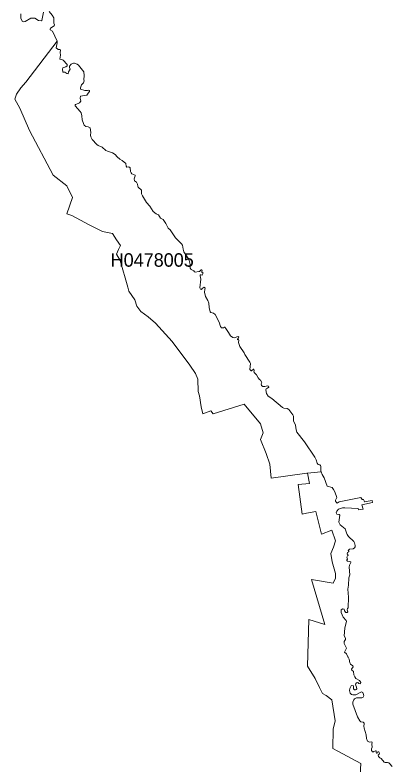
# Model space of a CAD drawing. Extents: x 369010 to 739155, y 6377141 to 6616555.
# Drawn here: x 462164 to 464965, y 6490804 to 6496362 of the extents above; entities that cross this region are included whole.
import ezdxf
from ezdxf.enums import TextEntityAlignment as Align

# ---------------------------------------------------------------- set-up
doc = ezdxf.new("R2010")
doc.units = 0
doc.header["$LTSCALE"] = 40
doc.layers.add('1', color=7, linetype='Continuous', lineweight=13)
doc.layers.add('2', color=7, linetype='Continuous')

msp = doc.modelspace()

# ---------------------------------------------------------------- linework, layer by layer
at = {"layer": '1'}
for points in [[(464337.03, 6491529.74), (464346.14, 6491876.14), (464466.29, 6491840.06), (464366.16, 6492172.56), (464528.52, 6492145.58), (464544.08, 6492181.82), (464544.08, 6492218.07), (464520.74, 6492303.47), (464510.48, 6492365.53), (464531.17, 6492412.21), (464544.08, 6492460.37), (464518.26, 6492537.99), (464440.47, 6492509.52), (464399.1, 6492677.84), (464329.25, 6492664.93), (464298.14, 6492656.82), (464267.19, 6492876.94), (464352.59, 6492884.72), (464337.03, 6492962.17), (464337.03, 6492962.34), (464333.23, 6492961.84), (464067.26, 6492926.09), (464057.5, 6493029.53), (464029.03, 6493107.32), (463987.65, 6493210.76), (464008.34, 6493262.56), (463988.65, 6493327.11), (463867.17, 6493474.58), (463636.79, 6493403.24), (463620.07, 6493424.59), (463559.5, 6493402.25), (463548.08, 6493454.22), (463535, 6493535.48), (463525.57, 6493566.93), (463522.59, 6493659.11), (463504.88, 6493700.98), (463463.34, 6493764.37), (463331.43, 6493940.3), (463207.14, 6494075.02), (463152.85, 6494121.53), (463098.57, 6494162.91), (463070.1, 6494201.8), (463055.54, 6494248.47), (463009.03, 6494313.18), (463001.25, 6494341.65), (462944.32, 6494540.92), (462918.5, 6494587.59), (462933.89, 6494621.19), (462946.97, 6494652.3), (462918.5, 6494693.35), (462887.38, 6494740.02), (462814.89, 6494755.58), (462713.94, 6494804.73), (462587.16, 6494874.57), (462549.92, 6494886.16), (462591.13, 6495007.47), (462548.43, 6495094.86), (462447.64, 6495174.3), (462271.21, 6495504.98), (462201.04, 6495669.82), (462163.97, 6495736.35), (462176.38, 6495773.76), (462206.33, 6495821.26), (462243.74, 6495863.63), (462477.1, 6496166.66), (462476.93, 6496168.65), (462442.34, 6496242.13), (462424.3, 6496250.74), (462424.63, 6496259.68), (462428.28, 6496264.15), (462454.43, 6496281.19), (462457.74, 6496288.81), (462452.27, 6496301.38), (462452.94, 6496340.11), (462441.35, 6496359.64), (462417.35, 6496388.44)], [(462376.31, 6496383.31), (462364.23, 6496320.91), (462360.58, 6496317.6), (462337.91, 6496321.24), (462312.59, 6496337.79), (462282.14, 6496338.46), (462240.59, 6496313.13), (462229.34, 6496311.31), (462220.73, 6496314.46), (462206.67, 6496335.97), (462206.33, 6496371.06)], [(462477.1, 6496166.66), (462243.74, 6495863.63), (462206.33, 6495821.26), (462176.38, 6495773.76), (462163.97, 6495736.35), (462201.04, 6495669.82), (462271.21, 6495504.98), (462447.64, 6495174.3), (462548.43, 6495094.86), (462591.13, 6495007.47), (462549.92, 6494886.16), (462587.16, 6494874.57), (462713.94, 6494804.73), (462814.89, 6494755.58), (462887.38, 6494740.02), (462918.5, 6494693.35), (462946.97, 6494652.3), (462933.89, 6494621.19), (462918.5, 6494587.59), (462944.32, 6494540.92), (463001.25, 6494341.65), (463009.03, 6494313.18), (463055.54, 6494248.47), (463070.1, 6494201.8), (463098.57, 6494162.91), (463152.85, 6494121.53), (463207.14, 6494075.02), (463331.43, 6493940.3), (463463.34, 6493764.37), (463504.88, 6493700.98), (463522.59, 6493659.11), (463525.57, 6493566.93), (463535, 6493535.48), (463548.08, 6493454.22), (463559.5, 6493402.25), (463620.07, 6493424.59), (463636.79, 6493403.24), (463867.17, 6493474.58), (463988.65, 6493327.11), (464008.34, 6493262.56), (463987.65, 6493210.76), (464029.03, 6493107.32), (464057.5, 6493029.53), (464067.26, 6492926.09), (464333.23, 6492961.84), (464337.03, 6492962.34), (464337.03, 6492962.17), (464436.67, 6492970.95), (464437.49, 6492971.11), (464436.5, 6492973.59), (464436.83, 6493012.49), (464433.19, 6493019.94), (464429.38, 6493023.25), (464415.32, 6493027.05), (464407.87, 6493035.33), (464402.08, 6493060.15), (464392.48, 6493080.01), (464313.7, 6493193.55), (464258.75, 6493267.2), (464253.29, 6493283.91), (464248.16, 6493317.35), (464233.26, 6493350.78), (464232.6, 6493384.21), (464227.47, 6493395.13), (464197.68, 6493435.02), (464185.76, 6493440.81), (464160.61, 6493444.62), (464151.01, 6493449.42), (464072.89, 6493516.28), (464045.08, 6493534.49), (464033.33, 6493553.19), (464027.87, 6493581.49), (464030.52, 6493587.61), (464041.11, 6493593.41), (464049.39, 6493601.19), (464047.57, 6493608.8), (464040.45, 6493609.79), (464019.27, 6493604.99), (464005.03, 6493606.32), (463995.76, 6493613.43), (463993.78, 6493624.03), (463997.42, 6493635.94), (463986.99, 6493653.15), (463981.53, 6493657.13), (463971.27, 6493670.2), (463959.35, 6493691.22), (463939.82, 6493708.6), (463937.84, 6493714.56), (463939.82, 6493721.67), (463937.84, 6493733.59), (463935.02, 6493734.25), (463920.79, 6493722), (463917.65, 6493722), (463909.21, 6493731.6), (463912.85, 6493776.95), (463909.87, 6493785.39), (463870.31, 6493842.82), (463866.84, 6493855.9), (463833.9, 6493902.57), (463825.29, 6493931.04)], [(462840.05, 6495357.18), (462811.91, 6495380.85), (462783.12, 6495392.44), (462773.19, 6495400.38), (462738.26, 6495439.11), (462727.34, 6495458.97), (462724.86, 6495469.89), (462726.68, 6495489.09), (462725.52, 6495508.29), (462721.55, 6495525.34), (462706.82, 6495532.29), (462689.61, 6495535.27), (462678.35, 6495543.54), (462672.56, 6495555.79), (462663.62, 6495584.59), (462660.81, 6495613.38), (462655.02, 6495635.06), (462647.9, 6495645.99), (462610.83, 6495689.02), (462610.83, 6495694.98), (462612.98, 6495697.62), (462634.49, 6495704.91), (462643.43, 6495711.36), (462653.03, 6495721.95), (462648.89, 6495743.97), (462651.54, 6495760.68), (462697.22, 6495766.14), (462706.82, 6495782.53), (462718.4, 6495794.94), (462717.08, 6495802.72), (462711.95, 6495803.88), (462701.69, 6495801.4), (462682.49, 6495801.06), (462651.54, 6495812.32), (462651.21, 6495822.58), (462658.16, 6495844.92), (462673.55, 6495858), (462678.35, 6495873.39), (462674.55, 6495879.84), (462677.36, 6495913.11), (462675.54, 6495939.43), (462635.82, 6495990.07), (462626.22, 6495997.35), (462607.02, 6496005.13), (462598.25, 6496004.47), (462582.53, 6495996.36), (462570.11, 6495983.28), (462569.12, 6495973.02), (462573.59, 6495960.61), (462561.18, 6495941.41), (462558.53, 6495925.69), (462549.26, 6495926.85), (462535.19, 6495937.44), (462522.78, 6495936.78), (462519.47, 6495938.43), (462516.32, 6495958.96), (462518.48, 6495970.54), (462540.98, 6495978.15), (462552.73, 6495985.6), (462552.73, 6495994.21), (462522.45, 6496026.48), (462512.85, 6496031.28), (462497.79, 6496033.6), (462501.59, 6496064.38), (462500.27, 6496083.58), (462502.26, 6496099.8), (462498.95, 6496104.93), (462484.55, 6496104.93), (462471.14, 6496118.83), (462471.47, 6496131.58), (462478.26, 6496154.91), (462477.1, 6496166.66)], [(463825.29, 6493931.04), (463827.28, 6493949.24), (463824.96, 6493952.72), (463818.01, 6493952.39), (463817.68, 6493956.52), (463824.3, 6493965.79), (463826.62, 6493972.58), (463821.16, 6493977.38), (463811.23, 6493974.73), (463795.17, 6493965.79), (463782.26, 6493967.78), (463764.06, 6493981.51), (463750.98, 6494007), (463729.96, 6494034.81), (463723.84, 6494044.41), (463718.71, 6494045.73), (463714.57, 6494040.27), (463698.85, 6494040.93), (463689.91, 6494051.52), (463681.64, 6494082.8), (463651.52, 6494138.41), (463639.1, 6494150.49), (463618.91, 6494154.13), (463614.11, 6494160.09), (463605.51, 6494190.55), (463603.52, 6494224.14), (463597.73, 6494243.51), (463580.18, 6494272.3), (463572.4, 6494305.57), (463574.06, 6494324.44), (463577.54, 6494334.04), (463570.25, 6494341.65), (463561.65, 6494337.84), (463554.7, 6494331.89), (463550.72, 6494324.44), (463541.12, 6494326.59), (463536.99, 6494338.18), (463543.77, 6494400.57), (463539.64, 6494425.4), (463540.79, 6494433.84), (463546.09, 6494433.34), (463554.03, 6494431.19), (463560.16, 6494440.79), (463559.5, 6494452.54), (463551.22, 6494451.71), (463550.89, 6494457.34), (463555.03, 6494466.28), (463552.54, 6494471.07), (463547.25, 6494469.92), (463535.66, 6494459.16), (463529.7, 6494458.17), (463503.06, 6494453.03), (463496.93, 6494456.84), (463492.14, 6494463.3), (463472.27, 6494473.72), (463465.65, 6494482.83), (463465.99, 6494511.62), (463459.2, 6494540.42), (463453.74, 6494552.83), (463418.49, 6494605.13), (463412.69, 6494624.33), (463408.56, 6494653.13), (463401.94, 6494665.05), (463356.42, 6494709.57), (463316.7, 6494767.82), (463301.31, 6494781.23), (463285.59, 6494815.16), (463264.24, 6494844.45), (463246.2, 6494854.38), (463230.8, 6494878.71), (463212.93, 6494885.33), (463191.08, 6494903.04), (463164.93, 6494943.92), (463141.1, 6494971.56), (463110.48, 6495019.56), (463104.36, 6495034.95), (463104.69, 6495060.93), (463080.03, 6495083.61), (463076.39, 6495092.54), (463075.23, 6495107.6), (463066.29, 6495120.84), (463052.06, 6495131.27), (463049.91, 6495145.67), (463057.85, 6495168.84), (463055.7, 6495174.63), (463032.86, 6495183.24), (463026.24, 6495190.02), (463022.27, 6495201.44), (463018.79, 6495228.75), (463010.52, 6495235.37), (462995.79, 6495232.89), (462990.99, 6495239.84), (462987.18, 6495260.03), (462959.87, 6495281.88), (462942, 6495292.14), (462923.3, 6495309.02), (462908.07, 6495326.73), (462888.71, 6495338.32), (462850.31, 6495351.06), (462840.05, 6495357.18)], [(464437.49, 6492971.11), (464436.67, 6492970.95), (464337.03, 6492962.17), (464352.59, 6492884.72), (464267.19, 6492876.94), (464298.14, 6492656.82), (464329.25, 6492664.93), (464399.1, 6492677.84), (464440.47, 6492509.52), (464518.26, 6492537.99), (464544.08, 6492460.37), (464531.17, 6492412.21), (464510.48, 6492365.53), (464520.74, 6492303.47), (464544.08, 6492218.07), (464544.08, 6492181.82), (464528.52, 6492145.58), (464366.16, 6492172.56), (464466.29, 6491840.06), (464346.14, 6491876.14), (464337.03, 6491529.74), (464393.97, 6491439.04), (464425.08, 6491371.85), (464448.25, 6491327.99), (464476.72, 6491312.6), (464518.26, 6491278.83), (464541.43, 6491123.59), (464528.52, 6491061.36), (464524.55, 6490917.87), (464563.44, 6490898.84), (464733.42, 6490806.98), (464720.01, 6490596.46)], [(464545.73, 6492753.47), (464545.07, 6492762.08), (464553.84, 6492782.44), (464540.93, 6492822.82), (464531.33, 6492841.52), (464520.08, 6492855.42), (464484, 6492865.02), (464461.16, 6492928.41), (464445.44, 6492952.74), (464437.49, 6492971.11)], [(464711.9, 6491408.09), (464719.02, 6491401.64), (464729.61, 6491398.49), (464732.26, 6491407.76), (464723.15, 6491422.99), (464696.51, 6491439.37), (464687.57, 6491450.3), (464681.78, 6491466.68), (464678.3, 6491489.19), (464665.72, 6491499.45), (464665.06, 6491508.06), (464677.31, 6491524.44), (464674.33, 6491532.88), (464656.29, 6491543.81), (464651.49, 6491553.74), (464647.35, 6491582.04), (464639.24, 6491597.43), (464637.09, 6491598.42), (464627.33, 6491620.93), (464611.27, 6491634.5), (464625.51, 6491662.8), (464609.45, 6491697.72), (464609.45, 6491711.63), (464619.71, 6491726.69), (464619.05, 6491737.28), (464608.79, 6491754.99), (464614.91, 6491812.92), (464626.5, 6491863.72), (464625.18, 6491867.53), (464602.01, 6491893.85), (464587.94, 6491929.26), (464587.94, 6491948.46), (464599.19, 6491954.59), (464609.45, 6491952.43), (464612.6, 6491941.51), (464621.04, 6491928.93), (464630.64, 6491929.26), (464637.42, 6491933.07), (464632.79, 6491948.46), (464633.12, 6491957.23), (464638.09, 6491963.36), (464641.23, 6492042.97), (464636.43, 6492100.89), (464641.23, 6492131.84), (464644.04, 6492184.47), (464651.82, 6492206.98), (464647.35, 6492264.91), (464650.17, 6492280.3), (464659.6, 6492299), (464658.61, 6492303.14), (464634.44, 6492308.27), (464629.31, 6492314.72), (464629.98, 6492319.85), (464633.12, 6492323.33), (464628.32, 6492339.38), (464633.78, 6492348.82), (464638.09, 6492350.31), (464639.91, 6492354.61), (464631.63, 6492364.54), (464634.77, 6492374.14), (464644.71, 6492378.94), (464645.04, 6492382.25), (464638.58, 6492388.04), (464649.01, 6492399.13), (464676.32, 6492401.12), (464687.24, 6492406.91), (464690.72, 6492415.02), (464691.05, 6492424.29), (464685.25, 6492445.47), (464680.12, 6492454.57), (464641.89, 6492492.47), (464631.63, 6492505.88), (464625.51, 6492520.11), (464622.53, 6492534.18), (464615.58, 6492549.08), (464580.82, 6492577.38), (464570.56, 6492598.56), (464576.02, 6492649.7), (464571.72, 6492655.99), (464555.66, 6492658.97), (464550.86, 6492666.75), (464554.17, 6492679.83), (464566.09, 6492694.22), (464597.87, 6492703.99), (464613.26, 6492705.31), (464712.89, 6492700.18), (464717.03, 6492690.42), (464749.3, 6492695.22), (464741.53, 6492726.17), (464819.64, 6492744.54), (464816.99, 6492760.26), (464758.9, 6492750), (464759.9, 6492752.48), (464752.45, 6492766.38), (464741.86, 6492766.88), (464734.08, 6492782.44), (464571.22, 6492749.5), (464558.31, 6492738.74), (464552.19, 6492743.21), (464545.73, 6492753.47)], [(464720.01, 6490596.46), (464733.42, 6490806.98), (464563.44, 6490898.84), (464524.55, 6490917.87), (464528.52, 6491061.36), (464541.43, 6491123.59), (464518.26, 6491278.83), (464476.72, 6491312.6), (464448.25, 6491327.99), (464425.08, 6491371.85), (464393.97, 6491439.04), (464337.03, 6491529.74)], [(464964.96, 6490784.8), (464946.92, 6490807.97), (464940.79, 6490812.44), (464930.2, 6490815.42), (464914.81, 6490815.42), (464906.04, 6490818.24), (464884.52, 6490845.54), (464874.92, 6490849.52), (464863.34, 6490859.45), (464862.67, 6490869.05), (464868.8, 6490876.82), (464871.11, 6490885.1), (464867.8, 6490894.7), (464860.19, 6490893.87), (464854.4, 6490885.43), (464850.26, 6490884.77), (464847.28, 6490889.9), (464845.96, 6490901.48), (464841.49, 6490901.82), (464830.24, 6490896.68), (464828.25, 6490893.87), (464820.97, 6490893.21), (464812.86, 6490904.46), (464813.19, 6490916.05), (464818.32, 6490928.13), (464815.17, 6490951.63), (464816.66, 6490964.54), (464813.85, 6490967.19), (464798.13, 6490965.2), (464782.07, 6490974.14), (464774.29, 6490992.51), (464773.63, 6491020.81), (464758.9, 6491069.64), (464756.59, 6491085.03), (464758.57, 6491103.07), (464757.25, 6491107.54), (464749.63, 6491114.32), (464734.08, 6491116.97), (464725.14, 6491123.59), (464708.42, 6491154.54), (464673.34, 6491247.06), (464672.68, 6491262.45), (464680.45, 6491281.15), (464687.24, 6491287.61), (464699.98, 6491294.39), (464741.19, 6491294.39), (464750.79, 6491300.18), (464755.1, 6491310.78), (464754.1, 6491318.39), (464747.65, 6491334.61), (464737.39, 6491338.75), (464694.85, 6491316.9), (464673.34, 6491316.24), (464664.07, 6491320.38), (464652.81, 6491329.64), (464648.68, 6491348.68), (464651.82, 6491364.07), (464660.59, 6491383.1), (464666.06, 6491386.25), (464677.81, 6491383.43), (464679.79, 6491377.64), (464679.13, 6491362.25), (464685.25, 6491355.13), (464694.19, 6491355.13), (464699.49, 6491357.28), (464702.3, 6491361.25), (464700.98, 6491373.83), (464694.85, 6491385.91), (464694.03, 6491396.84), (464700.98, 6491407.26), (464711.9, 6491408.09)]]:
    msp.add_lwpolyline(points, dxfattribs=at)

# ---------------------------------------------------------------- texts
at = {"layer": '2'}
msp.add_text('H0478005', height=100, dxfattribs=at).set_placement((463183.48, 6494493.98), align=Align.CENTER)

doc.saveas('drawing.dxf')
